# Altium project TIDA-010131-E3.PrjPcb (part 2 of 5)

## Sheet TIDA-010131-E3_LMK0482x _CLK_PWR.SchDoc: LMK0482x
size 431 x 279 mm; Date: Not shown in title block; ApprovedBy: Not shown in title block; CheckedBy: Not shown in title block; Author: Not shown in title block; CompanyName: Not shown in title block; DrawnBy: Avinash N; Engineer: Not shown in title block; Organization: Not shown in title block; Address1: Not shown in title block; Address2: Not shown in title block; Address3: Not shown in title block; Address4: Not shown in title block; DocumentNumber: 1; Revision: Use project parameter SCH_Rev; SheetNumber: 3; SheetTotal: 9; PageSetup: Record=PageOptions¦CenterHorizontal=True¦CenterVertical=True¦PrintScale=1.00¦XCorrection=1.00¦YCorrection=1.00¦PrintKind=0¦BorderSize=5000000¦LeftOffset=0¦BottomOffset=0¦Orientation=2¦PaperLength=1000¦PaperWidth=1000¦Scale=100¦PaperSource=15¦PrintQuality=600¦MediaType=1¦DitherType=10¦PaperKind=Letter¦PrintScaleMode=1
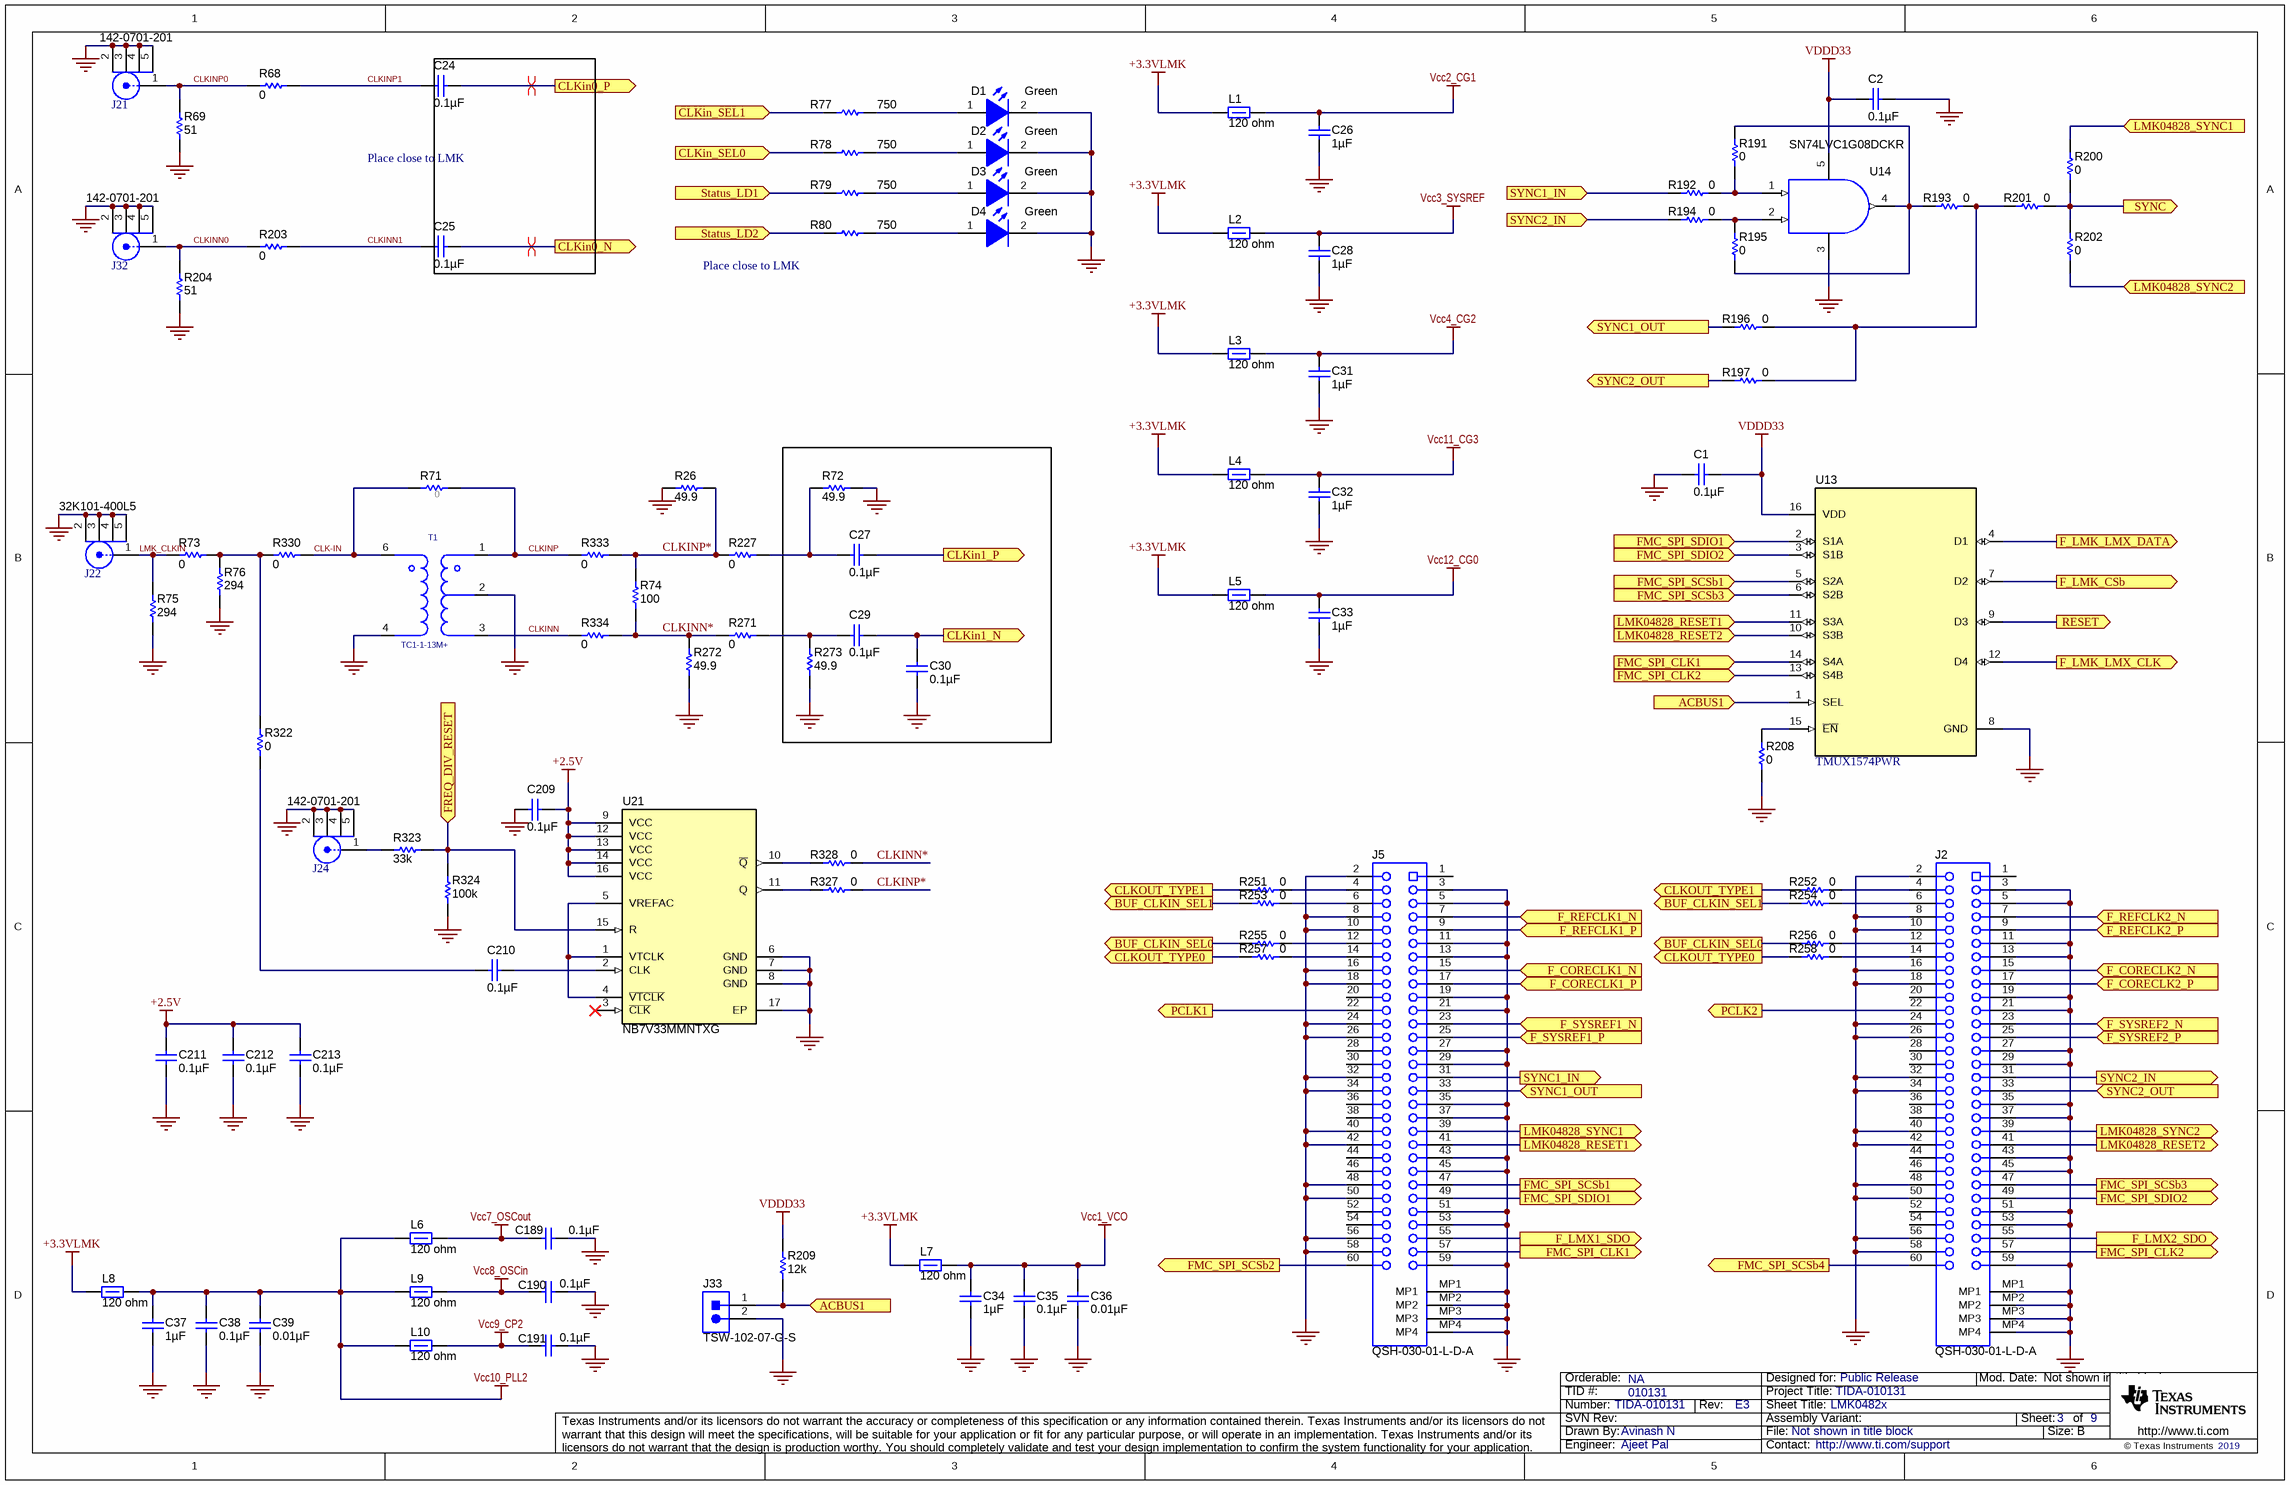
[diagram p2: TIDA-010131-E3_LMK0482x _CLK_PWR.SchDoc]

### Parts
C1  ValueDisplayed: 0.1µF  [0603]  (hidden comment: C0603C104J3RACTU)
C2  ValueDisplayed: 0.1µF  [0402]  (hidden comment: GRM155R71C104KA88D)
C24  ValueDisplayed: 0.1µF  [0201_033]  (hidden comment: GRM033R60J104KE19D)
C25  ValueDisplayed: 0.1µF  [0201_033]  (hidden comment: GRM033R60J104KE19D)
C26  ValueDisplayed: 1µF  [0402]  (hidden comment: C1005X7S1A105K050BC)
C27  ValueDisplayed: 0.1µF  [0201_033]  (hidden comment: GRM033R60J104KE19D)
C28  ValueDisplayed: 1µF  [0402]  (hidden comment: C1005X7S1A105K050BC)
C29  ValueDisplayed: 0.1µF  [0201_033]  (hidden comment: GRM033R60J104KE19D)
C30  ValueDisplayed: 0.1µF  [0201_033]  (hidden comment: GRM033R60J104KE19D)
C31  ValueDisplayed: 1µF  [0402]  (hidden comment: C1005X7S1A105K050BC)
C32  ValueDisplayed: 1µF  [0402]  (hidden comment: C1005X7S1A105K050BC)
C33  ValueDisplayed: 1µF  [0402]  (hidden comment: C1005X7S1A105K050BC)
C34  ValueDisplayed: 1µF  [0402]  (hidden comment: C1005X7S1A105K050BC)
C35  ValueDisplayed: 0.1µF  [0402]  (hidden comment: GRM155R71C104KA88D)
C36  ValueDisplayed: 0.01µF  [0402]  (hidden comment: GRM155R71E103KA01D)
C37  ValueDisplayed: 1µF  [0402]  (hidden comment: C1005X7S1A105K050BC)
C38  ValueDisplayed: 0.1µF  [0402]  (hidden comment: GRM155R71C104KA88D)
C39  ValueDisplayed: 0.01µF  [0402]  (hidden comment: GRM155R71E103KA01D)
C189  ValueDisplayed: 0.1µF  [0402]  (hidden comment: C1005X7R1E104M050BB)
C190  ValueDisplayed: 0.1µF  [0402]  (hidden comment: C1005X7R1E104M050BB)
C191  ValueDisplayed: 0.1µF  [0402]  (hidden comment: C1005X7R1E104M050BB)
C209  ValueDisplayed: 0.1µF  [0402]  (hidden comment: C1005X7R1E104M050BB)
C210  ValueDisplayed: 0.1µF  [0603]  (hidden comment: C0603C104J3RACTU)
C211  ValueDisplayed: 0.1µF  [0402]  (hidden comment: C1005X7R1E104M050BB)
C212  ValueDisplayed: 0.1µF  [0402]  (hidden comment: C1005X7R1E104M050BB)
C213  ValueDisplayed: 0.1µF  [0402]  (hidden comment: C1005X7R1E104M050BB)
D1  value Green  [LTST-C191_Green]  (hidden comment: LTST-C191TGKT)
D2  value Green  [LTST-C191_Green]  (hidden comment: LTST-C191TGKT)
D3  value Green  [LTST-C191_Green]  (hidden comment: LTST-C191TGKT)
D4  value Green  [LTST-C191_Green]  (hidden comment: LTST-C191TGKT)
J2  QSH-030-01-L-D-A  [Samtec_QSH-030-01-X-D-A]
J5  QSH-030-01-L-D-A  [Samtec_QSH-030-01-X-D-A]
J21  142-0701-201  [Johnson_142-0701-20x]
J22  32K101-400L5  [Rosenberger_32K101-400L5]
J24  142-0701-201  [Johnson_142-0701-20x]
J32  142-0701-201  [Johnson_142-0701-20x]
J33  TSW-102-07-G-S  [TSW-102-07-G-S]
L1  ValueDisplayed: 120 ohm  [0603]  (hidden comment: BLM18AG121SN1D)
L2  ValueDisplayed: 120 ohm  [0603]  (hidden comment: BLM18AG121SN1D)
L3  ValueDisplayed: 120 ohm  [0603]  (hidden comment: BLM18AG121SN1D)
L4  ValueDisplayed: 120 ohm  [0603]  (hidden comment: BLM18AG121SN1D)
L5  ValueDisplayed: 120 ohm  [0603]  (hidden comment: BLM18AG121SN1D)
L6  ValueDisplayed: 120 ohm  [0603]  (hidden comment: BLM18AG121SN1D)
L7  ValueDisplayed: 120 ohm  [0603]  (hidden comment: BLM18AG121SN1D)
L8  ValueDisplayed: 120 ohm  [0603]  (hidden comment: BLM18AG121SN1D)
L9  ValueDisplayed: 120 ohm  [0603]  (hidden comment: BLM18AG121SN1D)
L10  ValueDisplayed: 120 ohm  [0603]  (hidden comment: BLM18AG121SN1D)
R26  ValueDisplayed: 49.9  [0201]  (hidden comment: CRCW020149R9FKED)
R68  ValueDisplayed: 0  [0201]  (hidden comment: ERJ-1GN0R00C)
R69  ValueDisplayed: 51  [0201]  (hidden comment: RC0201JR-0751RL)
R71  ValueDisplayed: 0  [0603]  (hidden comment: CRCW06030000Z0EA)
R72  ValueDisplayed: 49.9  [0201]  (hidden comment: CRCW020149R9FKED)
R73  ValueDisplayed: 0  [0402]  (hidden comment: CRCW04020000Z0ED)
R74  ValueDisplayed: 100  [0201]  (hidden comment: RC0201FR-07100RL)
R75  ValueDisplayed: 294  [0402]  (hidden comment: CRCW0402294RFKED)
R76  ValueDisplayed: 294  [0402]  (hidden comment: CRCW0402294RFKED)
R77  ValueDisplayed: 750  [0603]  (hidden comment: CRCW0603750RFKEA)
R78  ValueDisplayed: 750  [0603]  (hidden comment: CRCW0603750RFKEA)
R79  ValueDisplayed: 750  [0603]  (hidden comment: CRCW0603750RFKEA)
R80  ValueDisplayed: 750  [0603]  (hidden comment: CRCW0603750RFKEA)
R191  ValueDisplayed: 0  [0402]  (hidden comment: CRCW04020000Z0ED)
R192  ValueDisplayed: 0  [0402]  (hidden comment: CRCW04020000Z0ED)
R193  ValueDisplayed: 0  [0402]  (hidden comment: CRCW04020000Z0ED)
R194  ValueDisplayed: 0  [0402]  (hidden comment: CRCW04020000Z0ED)
R195  ValueDisplayed: 0  [0402]  (hidden comment: CRCW04020000Z0ED)
R196  ValueDisplayed: 0  [0402]  (hidden comment: CRCW04020000Z0ED)
R197  ValueDisplayed: 0  [0402]  (hidden comment: CRCW04020000Z0ED)
R200  ValueDisplayed: 0  [0402]  (hidden comment: CRCW04020000Z0ED)
R201  ValueDisplayed: 0  [0402]  (hidden comment: CRCW04020000Z0ED)
R202  ValueDisplayed: 0  [0402]  (hidden comment: CRCW04020000Z0ED)
R203  ValueDisplayed: 0  [0201]  (hidden comment: ERJ-1GN0R00C)
R204  ValueDisplayed: 51  [0201]  (hidden comment: RC0201JR-0751RL)
R208  ValueDisplayed: 0  [0402]  (hidden comment: CRCW04020000Z0ED)
R209  ValueDisplayed: 12k  [0402]  (hidden comment: CRCW040212K0JNED)
R227  ValueDisplayed: 0  [0201]  (hidden comment: ERJ-1GN0R00C)
R251  ValueDisplayed: 0  [0402]  (hidden comment: CRCW04020000Z0ED)
R252  ValueDisplayed: 0  [0402]  (hidden comment: CRCW04020000Z0ED)
R253  ValueDisplayed: 0  [0402]  (hidden comment: CRCW04020000Z0ED)
R254  ValueDisplayed: 0  [0402]  (hidden comment: CRCW04020000Z0ED)
R255  ValueDisplayed: 0  [0402]  (hidden comment: CRCW04020000Z0ED)
R256  ValueDisplayed: 0  [0402]  (hidden comment: CRCW04020000Z0ED)
R257  ValueDisplayed: 0  [0402]  (hidden comment: CRCW04020000Z0ED)
R258  ValueDisplayed: 0  [0402]  (hidden comment: CRCW04020000Z0ED)
R271  ValueDisplayed: 0  [0201]  (hidden comment: ERJ-1GN0R00C)
R272  ValueDisplayed: 49.9  [0201]  (hidden comment: CRCW020149R9FKED)
R273  ValueDisplayed: 49.9  [0201]  (hidden comment: CRCW020149R9FKED)
R322  ValueDisplayed: 0  [0402]  (hidden comment: CRCW04020000Z0ED)
R323  ValueDisplayed: 33k  [0402]  (hidden comment: CRCW040233K0JNED)
R324  ValueDisplayed: 100k  [0402]  (hidden comment: CRCW0402100KFKED)
R327  ValueDisplayed: 0  [0201]  (hidden comment: ERJ-1GN0R00C)
R328  ValueDisplayed: 0  [0201]  (hidden comment: ERJ-1GN0R00C)
R330  ValueDisplayed: 0  [0402]  (hidden comment: CRCW04020000Z0ED)
R333  ValueDisplayed: 0  [0201]  (hidden comment: ERJ-1GN0R00C)
R334  ValueDisplayed: 0  [0201]  (hidden comment: ERJ-1GN0R00C)
T1  TC1-1-13M+  [TFMR_5_150x150_50]
U13  TMUX1574PWR  [PW0016A_N]
U14  SN74LVC1G08DCKR  [DCK0005A_N]
U21  NB7V33MMNTXG  [QFN16-3x3MM_0_5]

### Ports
ACBUS1 (in), BUF_CLKIN_SEL0 (out), BUF_CLKIN_SEL1 (out), CLKin0_N (out), CLKin0_P (out), CLKin1_N (out), CLKin1_P (out), CLKin_SEL0 (in), CLKin_SEL1 (in), CLKOUT_TYPE0 (out), CLKOUT_TYPE1 (out), F_CORECLK1_N (in), F_CORECLK1_P (in), F_CORECLK2_N (in), F_CORECLK2_P (in), F_LMK_CSb (out), F_LMK_LMX_CLK (out), F_LMK_LMX_DATA (out), F_LMX1_SDO (out), F_LMX2_SDO (out), F_REFCLK1_N (in), F_REFCLK1_P (in), F_REFCLK2_N (in), F_REFCLK2_P (in), F_SYSREF1_N (in), F_SYSREF1_P (in), F_SYSREF2_N (in), F_SYSREF2_P (in), FMC_SPI_CLK1 (in), FMC_SPI_CLK1 (out), FMC_SPI_CLK2 (in), FMC_SPI_CLK2 (out), FMC_SPI_SCSb1 (in), FMC_SPI_SCSb1 (out), FMC_SPI_SCSb2 (out), FMC_SPI_SCSb3 (in), FMC_SPI_SCSb3 (out), FMC_SPI_SCSb4 (out), FMC_SPI_SDIO1 (in), FMC_SPI_SDIO1 (out), FMC_SPI_SDIO2 (in), FMC_SPI_SDIO2 (out), FREQ_DIV_RESET (in), LMK04828_RESET1 (in), LMK04828_RESET1 (out), LMK04828_RESET2 (in), LMK04828_RESET2 (out), LMK04828_SYNC1 (in), LMK04828_SYNC1 (out), LMK04828_SYNC2 (in), LMK04828_SYNC2 (out), PCLK1 (out), PCLK2 (out), RESET (out), Status_LD1 (in), Status_LD2 (in), SYNC1_IN (in), SYNC1_IN (out), SYNC1_OUT (in), SYNC1_OUT (out), SYNC2_IN (in), SYNC2_IN (out), SYNC2_OUT (in), SYNC2_OUT (out), SYNC (out)

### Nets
+2.5V: C209.2 C211.2 C212.2 C213.2 U21.9(VCC) U21.12(VCC) U21.13(VCC) U21.14(VCC) U21.16(VCC)
+3.3VLMK: L1.1 L2.1 L3.1 L4.1 L5.1 L7.1 L8.1
GND: C1.1 C2.2 C26.2 C28.2 C30.1 C31.2 C32.2 C33.2 C34.2 C35.2 C36.2 C37.2 C38.2 C39.2 C189.2 C190.1 C191.1 C209.1 C211.1 C212.1 C213.1 D1.2(K) D2.2(K) D3.2(K) D4.2(K) J2.2 J2.3 J2.5 J2.8 J2.10 J2.11 J2.13 J2.16 J2.18 J2.19 J2.21 J2.24 J2.26 J2.27 J2.29 J2.32 J2.34 J2.35 J2.37 J2.40 J2.42 J2.43 J2.45 J2.48 J2.50 J2.51 J2.53 J2.56 J2.58 J2.59 J2.MP1 J2.MP2 J2.MP3 J2.MP4 J5.2 J5.3 J5.5 J5.8 J5.10 J5.11 J5.13 J5.16 J5.18 J5.19 J5.21 J5.24 J5.26 J5.27 J5.29 J5.32 J5.34 J5.35 J5.37 J5.40 J5.42 J5.43 J5.45 J5.48 J5.50 J5.51 J5.53 J5.56 J5.58 J5.59 J5.MP1 J5.MP2 J5.MP3 J5.MP4 J21.2 J21.3 J21.4 J21.5 J22.2 J22.3 J22.4 J22.5 J24.2 J24.3 J24.4 J24.5 J32.2 J32.3 J32.4 J32.5 J33.2 R26.1 R69.1 R72.2 R75.1 R76.1 R204.1 R208.1 R272.1 R273.1 R324.1 T1.2(secondary_ct) T1.4(primary) U13.8(GND) U14.3(V-) U21.6(GND) U21.7(GND) U21.8(GND) U21.17(EP)
Vcc1_VCO: C34.1 C35.1 C36.1 L7.2
Vcc2_CG1: C26.1 L1.2
Vcc3_SYSREF: C28.1 L2.2
Vcc4_CG2: C31.1 L3.2
Vcc7_OSCout: C189.1 L6.2
Vcc8_OSCin: C190.2 L9.2
Vcc9_CP2: C191.2 L10.2
Vcc10_PLL2: C37.1 C38.1 C39.1 L6.1 L8.2 L9.1 L10.1
Vcc11_CG3: C32.1 L4.2
Vcc12_CG0: C33.1 L5.2
VDDD33: C1.2 C2.1 R209.2 U13.16(VDD) U14.5(V+)
ACBUS1: J33.1 R209.1 U13.1(SEL) ; port ACBUS1
BUF_CLKIN_SEL0: R255.1 R256.1 ; port BUF_CLKIN_SEL0
BUF_CLKIN_SEL1: R253.1 R254.1 ; port BUF_CLKIN_SEL1
CLK-IN: R71.1 R330.2 T1.6(primary_dot)
CLKin0_N: C25.2 ; port CLKin0_N
CLKin0_P: C24.2 ; port CLKin0_P
CLKin1_N: C29.2 C30.2 ; port CLKin1_N
CLKin1_P: C27.2 ; port CLKin1_P
CLKin_SEL0: R78.1 ; port CLKin_SEL0
CLKin_SEL1: R77.1 ; port CLKin_SEL1
CLKINN: R334.1 T1.3(secondary)
CLKINN0: J32.1 R203.1 R204.2
CLKINN1: C25.1 R203.2
CLKINN*: R74.1 R271.1 R272.2 R328.1 R334.2
CLKINP: R71.2 R333.1 T1.1(secondary_dot)
CLKINP0: J21.1 R68.1 R69.2
CLKINP1: C24.1 R68.2
CLKINP*: R26.2 R74.2 R227.1 R327.1 R333.2
CLKOUT_TYPE0: R257.1 R258.1 ; port CLKOUT_TYPE0
CLKOUT_TYPE1: R251.1 R252.1 ; port CLKOUT_TYPE1
F_CORECLK1_N: J5.15 ; port F_CORECLK1_N
F_CORECLK1_P: J5.17 ; port F_CORECLK1_P
F_CORECLK2_N: J2.15 ; port F_CORECLK2_N
F_CORECLK2_P: J2.17 ; port F_CORECLK2_P
F_LMK_CSb: U13.7(D2) ; port F_LMK_CSb
F_LMK_LMX_CLK: U13.12(D4) ; port F_LMK_LMX_CLK
F_LMK_LMX_DATA: U13.4(D1) ; port F_LMK_LMX_DATA
F_LMX1_SDO: J5.55 ; port F_LMX1_SDO
F_LMX2_SDO: J2.55 ; port F_LMX2_SDO
F_REFCLK1_N: J5.7 ; port F_REFCLK1_N
F_REFCLK1_P: J5.9 ; port F_REFCLK1_P
F_REFCLK2_N: J2.7 ; port F_REFCLK2_N
F_REFCLK2_P: J2.9 ; port F_REFCLK2_P
F_SYSREF1_N: J5.23 ; port F_SYSREF1_N
F_SYSREF1_P: J5.25 ; port F_SYSREF1_P
F_SYSREF2_N: J2.23 ; port F_SYSREF2_N
F_SYSREF2_P: J2.25 ; port F_SYSREF2_P
FMC_SPI_CLK1: J5.57 U13.14(S4A) ; port FMC_SPI_CLK1
FMC_SPI_CLK2: J2.57 U13.13(S4B) ; port FMC_SPI_CLK2
FMC_SPI_SCSb1: J5.47 U13.5(S2A) ; port FMC_SPI_SCSb1
FMC_SPI_SCSb2: J5.60 ; port FMC_SPI_SCSb2
FMC_SPI_SCSb3: J2.47 U13.6(S2B) ; port FMC_SPI_SCSb3
FMC_SPI_SCSb4: J2.60 ; port FMC_SPI_SCSb4
FMC_SPI_SDIO1: J5.49 U13.2(S1A) ; port FMC_SPI_SDIO1
FMC_SPI_SDIO2: J2.49 U13.3(S1B) ; port FMC_SPI_SDIO2
FREQ_DIV_RESET: R323.2 R324.2 U21.15(R) ; port FREQ_DIV_RESET
LMK04828_RESET1: J5.41 U13.11(S3A) ; port LMK04828_RESET1
LMK04828_RESET2: J2.41 U13.10(S3B) ; port LMK04828_RESET2
LMK04828_SYNC1: J5.39 R200.1 ; port LMK04828_SYNC1
LMK04828_SYNC2: J2.39 R202.1 ; port LMK04828_SYNC2
LMK_CLKIN: J22.1 R73.1 R75.2
PCLK1: J5.22 ; port PCLK1
PCLK2: J2.22 ; port PCLK2
RESET: U13.9(D3) ; port RESET
Status_LD1: R79.1 ; port Status_LD1
Status_LD2: R80.1 ; port Status_LD2
SYNC: R200.2 R201.2 R202.2 ; port SYNC
SYNC1_IN: J5.31 R192.1 ; port SYNC1_IN
SYNC1_OUT: J5.33 R196.1 ; port SYNC1_OUT
SYNC2_IN: J2.31 R194.1 ; port SYNC2_IN
SYNC2_OUT: J2.33 R197.1 ; port SYNC2_OUT
NetC27_1: C27.1 R72.1 R227.2
NetC29_1: C29.1 R271.2 R273.2
NetC210_1: C210.1 R322.1
NetC210_2: C210.2 U21.2(CLK)
NetD1_1: D1.1(A) R77.2
NetD2_1: D2.1(A) R78.2
NetD3_1: D3.1(A) R79.2
NetD4_1: D4.1(A) R80.2
NetJ2_4: J2.4 R252.2
NetJ2_6: J2.6 R254.2
NetJ2_12: J2.12 R256.2
NetJ2_14: J2.14 R258.2
NetJ5_4: J5.4 R251.2
NetJ5_6: J5.6 R253.2
NetJ5_12: J5.12 R255.2
NetJ5_14: J5.14 R257.2
NetJ24_1: J24.1 R323.1
NetR73_2: R73.2 R76.2 R322.2 R330.1
NetR191_1: R191.1 R192.2 U14.1(A)
NetR191_2: R191.2 R193.1 R195.1 U14.4(Y)
NetR193_2: R193.2 R196.2 R197.2 R201.1
NetR194_2: R194.2 R195.2 U14.2(B)
NetR208_2: R208.2 U13.15(~{EN})
NetR327_2: R327.2 U21.11(Q)
NetR328_2: R328.2 U21.10(~{Q})
NetU21_1: U21.1(VTCLK) U21.4(~{VTCLK}) U21.5(VREFAC)

Not connected (* = marked no-connect by the designer): J2 1 20 28 30 36 38 44 46 52 54; J5 1 20 28 30 36 38 44 46 52 54; U21 3(~{CLK})*

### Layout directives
differential pair: CLKin0_N, CLKin0_P

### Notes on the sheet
- Place close to LMK
- (near R80) Place close to LMK

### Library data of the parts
C1 = C0603C104J3RACTU: CAP, CERM, 0.1uF, 25V, +/-5%, X7R, 0603; Manufacturer: Kemet; Polarized: N; TaMax_C: 125; TaMin_C: -55; Tolerance_%: 5; VDC_V: 25; Cap_F: 0.0000001; CompType: Capacitor; Value1: Unknown; U/M: EA
C2 C35 C38 = GRM155R71C104KA88D: CAP, CERM, 0.1 µF, 16 V, +/- 10%, X7R, 0402; Manufacturer: MuRata; Polarized: N; CompType: Capacitor; Value: 0.1uF; U/M: EA; Cap_F: 0.0000001; Tolerance_%: 10; Value1: Unknown; VDC_V: 16; Value2: 16V; TaMin_C: -55; TaMax_C: 125; SizeArea_mm2: 0.5; SizeAreaWB_mm2: 3; SizeX_mm: 1; SizeZ_mm: 0.6; AEC Category: Q200
C24 = grm033r60j104ke19d: CAP, CERM, 0.1 µF, 6.3 V, +/- 10%, X5R, 0201; Manufacturer: MuRata; Polarized: N; CompType: Capacitor; Value: 0.1uF; U/M: EA; Cap_F: 0.0000001; Tolerance_%: 10; Value1: Unknown; VDC_V: 6.3; Value2: 6.3V; TaMin_C: -55; TaMax_C: 85; Cap_Case: 0201; SizeArea_mm2: 0.18; SizeAreaWB_mm2: 2.08; SizeX_mm: 0.6; SizeY_mm: 0.3; SizeZ_mm: 0.33; AEC Category: Q200
C25 C27 C29 C30 = GRM033R60J104KE19D: CAP, CERM, 0.1 µF, 6.3 V, +/- 10%, X5R, 0201; Manufacturer: MuRata; Polarized: N; CompType: Capacitor; Value: 0.1uF; U/M: EA; Cap_F: 0.0000001; Tolerance_%: 10; Value1: Unknown; VDC_V: 6.3; Value2: 6.3V; TaMin_C: -55; TaMax_C: 85; Cap_Case: 0201; SizeArea_mm2: 0.18; SizeAreaWB_mm2: 2.08; SizeX_mm: 0.6; SizeY_mm: 0.3; SizeZ_mm: 0.33; AEC Category: Q200
C26 C28 C31-C34 C37 = C1005X7S1A105K050BC: CAP, CERM, 1 µF, 10 V, +/- 10%, X7S, 0402; Manufacturer: TDK; Polarized: N; CompType: Capacitor; Value: 1uF; U/M: EA; Cap_F: 0.000001; Tolerance_%: 10; ESR_ohm: 0.011416; Value1: 0.011416 ohm; Value2: 10V; IRMS_A: 1.483; TaMin_C: -55; TaMax_C: 125; SizeArea_mm2: 0.5; SizeAreaWB_mm2: 3; SizeX_mm: 1; SizeZ_mm: 0.6; AEC Category: Q200
C36 C39 = GRM155R71E103KA01D: CAP, CERM, 0.01 µF, 25 V, +/- 10%, X7R, 0402; Manufacturer: MuRata; Polarized: N; CompType: Capacitor; Value: 0.01uF; U/M: EA; Cap_F: 0.00000001; Tolerance_%: 10; Value1: Unknown; VDC_V: 25; Value2: 25V; TaMin_C: -55; TaMax_C: 125; SizeArea_mm2: 0.5; SizeAreaWB_mm2: 3; SizeX_mm: 1; SizeZ_mm: 0.6; AEC Category: Q200
C189-C191 = C1005X7R1E104M050BB: CAP, CERM, 0.1 µF, 25 V, +/- 20%, X7R, 0402; Manufacturer: TDK; Polarized: N; TaMax_C: 125; TaMin_C: -55; Tolerance_%: 20; VDC_V: 25; Cap_F: 0.0000001; CompType: Capacitor; Value: 0.1uF; Value1: Unknown; Value2: 25V; U/M: EA; SizeArea_mm2: 0.5; SizeAreaWB_mm2: 3; SizeX_mm: 1; SizeZ_mm: 0.6; AEC Category: Q200
C209 C211-C213 = C1005X7R1E104M050BB: CAP, CERM, 0.1 µF, 25 V,+/- 20%, X7R, 0402; Manufacturer: TDK; Polarized: N; TaMax_C: 125; TaMin_C: -55; Tolerance_%: 20; VDC_V: 25; Cap_F: 0.0000001; CompType: Capacitor; Value: 0.1uF; Value2: 25V; U/M: EA; SizeArea_mm2: 0.5; SizeAreaWB_mm2: 3; SizeX_mm: 1; SizeZ_mm: 0.6; AEC Category: Q200; Green_Lifecycle: NRND; Green_REACh: Passed
C210 = C0603C104J3RACTU: CAP, CERM, 0.1 µF, 25 V,+/- 5%, X7R, 0603; Manufacturer: Kemet; Polarized: N; TaMax_C: 125; TaMin_C: -55; Tolerance_%: 5; VDC_V: 25; Cap_F: 0.0000001; CompType: Capacitor; Value: 0.1uF; Value2: 25V; U/M: EA; SizeArea_mm2: 1.28; SizeAreaWB_mm2: 4.68; SizeX_mm: 1.6; SizeY_mm: 0.8; SizeZ_mm: 1; AEC Category: Q200; Green_Lifecycle: Active; Green_REACh: Passed
D1-D4 = LTST-C191TGKT: LED, Green, SMD; Manufacturer: Lite-On; Type: InGaN; Vf_V: 3.2; Value2: 3.2V; Io_A: 0.02; Value1: W; U/M: EA
J2 J5 = QSH-030-01-L-D-A: Receptacle, 0.5 mm, 30x2, Gold, TH; Manufacturer: Samtec; SymbolCreator: Altium; Pitch_mm: 0.5; Gender: Female; Shrouded: N; Row_Count: 2; RowSpacing_mm: 5.73
J21 J24 J32 = 142-0701-201: Connector, TH, SMA; Manufacturer: Emerson Network Power; SymbolCreator: X0208326
J22 = CMP-0077743-1: SMA, 50 Ohm, Gold, TH; Manufacturer: Rosenberger; Gender: Female; Voltage_V: 480V
J33 = TSW-102-07-G-S: Header, 100mil, 2x1, Gold, TH; Manufacturer: Samtec; SymbolCreator: a0412235; Pitch_mm: 2.54; Gender: Male; Shrouded: N; Row_Count: 1; Current_A: 6.3; Voltage_V: 550; Cert_CSA: Y
L1-L10 = BLM18AG121SN1D: Ferrite Bead, 120 ohm @ 100 MHz, 0.5 A, 0603; Manufacturer: MuRata; Value: 120 ohm; Imax_A: 0.5; DCR_ohm: 0.18; Value1: 0.18 ohm; Value2: 0.5A; SizeAreaWB_mm2: 4.68; SizeArea_mm2: 1.28; SizeX_mm: 1.6; SizeY_mm: 0.8; SizeZ_mm: 1; ZTyp@100MHz_Ohm: 120
R26 R72 R272 R273 = CRCW020149R9FKED: RES, 49.9, 1%, 0.05 W, 0201; Manufacturer: Vishay-Dale; CompType: Resistor; Value: 49.9; Value_Code: 49R9; Tolerance_%: 1; Power_W: 0.05; Value2: 0.05W; VDC_V: 30; TempCo: 100 ppm/C; SizeArea_mm2: 0.18; SizeX_mm: 0.6; SizeY_mm: 0.3; SizeZ_mm: 0.26; EIA_Code: E96; U/M: EA; AEC Category: Q200; AEC Qualified: N
R68 R203 R227 R271 R327 R328 R333 R334 = ERJ-1GN0R00C: RES, 0, 5%, 0.05 W, AEC-Q200 Grade 0, 0201; Manufacturer: Panasonic; CompType: Resistor; Tolerance_%: 5; Power_W: 0.05; Value: 0; U/M: EA; Value_Code: 0000; Value2: 0.05W; EIA_Code: E24; TempCo: ppm/C; SizeArea_mm2: 0.18; SizeX_mm: 0.6; SizeY_mm: 0.3; SizeZ_mm: 0.26; AEC Category: Q200; AEC Qualified: Y
R69 R204 = RC0201JR-0751RL: RES, 51, 5%, 0.05 W, 0201; Manufacturer: Yageo America; CompType: Resistor; Value: 51; Value_Code: 51R0; Tolerance_%: 5; Power_W: 0.05; Value2: 0.05W; VDC_V: 25; TempCo: 200 ppm/C; SizeArea_mm2: 0.18; SizeX_mm: 0.6; SizeY_mm: 0.3; SizeZ_mm: 0.26; EIA_Code: E24; U/M: EA; AEC Category: Q200; AEC Qualified: N
R71 = CRCW06030000Z0EA: RES, 0, 5%, 0.1 W, 0603; Manufacturer: Vishay-Dale; CompType: Resistor; Tolerance_%: 5; VDC_V: 75; Power_W: 0.1; Value: 0; U/M: EA; Value_Code: 0000; Value2: 0.1W; EIA_Code: E24; TempCo: 200 ppm/C; SizeArea_mm2: 1.28; SizeX_mm: 1.6; SizeY_mm: 0.8; SizeZ_mm: 1; AEC Category: Q200
R73 R322 R330 = CRCW04020000Z0ED: RES, 0, 5%, 0.063 W, 0402; Manufacturer: Vishay-Dale; CompType: Resistor; Tolerance_%: 5; VDC_V: 50; Power_W: 0.063; Value: 0; U/M: EA; Value_Code: 0000; Value2: 0.063W; EIA_Code: E24; TempCo: 200 ppm/C; SizeArea_mm2: 0.5; SizeX_mm: 1; SizeZ_mm: 0.6; AEC Category: Q200; Green_Lifecycle: Active; Green_REACh: Passed
R74 = rc0201fr-07100rl: RES, 100, 1%, 0.05 W, 0201; Manufacturer: Yageo America; CompType: Resistor; Value: 100; Value_Code: 100R; Tolerance_%: 1; Power_W: 0.05; Value2: 0.05W; VDC_V: 25; TempCo: 200 ppm/C; SizeArea_mm2: 0.18; SizeX_mm: 0.6; SizeY_mm: 0.3; SizeZ_mm: 0.26; EIA_Code: E96; U/M: EA; AEC Category: Q200; AEC Qualified: N
R75 R76 = CRCW0402294RFKED: RES, 294, 1%, 0.063 W, 0402; Manufacturer: Vishay-Dale; CompType: Resistor; Value: 294; Value_Code: 294R; Tolerance_%: 1; Power_W: 0.063; Value2: 0.063W; VDC_V: 50; TempCo: 100 ppm/C; SizeArea_mm2: 0.5; SizeZ_mm: 0.6; EIA_Code: E96; U/M: EA; AEC Category: Q200
R77-R80 = CRCW0603750RFKEA: RES, 750, 1%, 0.1 W, 0603; Manufacturer: Vishay-Dale; CompType: Resistor; Value: 750; Value_Code: 750R; Tolerance_%: 1; Power_W: 0.1; Value2: 0.1W; VDC_V: 75; TempCo: 100 ppm/C; SizeArea_mm2: 1.28; SizeX_mm: 1.6; SizeY_mm: 0.8; EIA_Code: E96; U/M: EA; AEC Category: Q200
R191-R197 R200-R202 R208 R251-R258 = CRCW04020000Z0ED: RES, 0, 5%, 0.063 W, 0402; Manufacturer: Vishay-Dale; CompType: Resistor; Value: 0; Value_Code: 0000; Tolerance_%: 5; Power_W: 0.063; Value2: 0.063W; VDC_V: 50; TempCo: 200 ppm/C; SizeArea_mm2: 0.5; SizeX_mm: 1; SizeZ_mm: 0.6; EIA_Code: E24; U/M: EA; AEC Category: Q200
R209 = CRCW040212K0JNED: RES, 12 k, 5%, 0.063 W, 0402; Manufacturer: Vishay-Dale; CompType: Resistor; Value: 12k; Res_ohm: 12000; Value_Code: 12k0; Tolerance_%: 5; Power_W: 0.063; Value2: 0.063W; VDC_V: 50; TempCo: 200 ppm/C; EIA_Code: E24; U/M: EA; AEC Category: Q200
R323 = CRCW040233K0JNED: RES, 33 k, 5%, 0.063 W, 0402; Manufacturer: Vishay-Dale; CompType: Resistor; Value: 33k; Res_ohm: 33000; Value_Code: 33k0; Tolerance_%: 5; Power_W: 0.063; Value2: 0.063W; VDC_V: 50; TempCo: 200 ppm/C; SizeArea_mm2: 0.5; SizeX_mm: 1; SizeZ_mm: 0.6; EIA_Code: E24; U/M: EA; AEC Category: Q200; Green_Lifecycle: Active; Green_REACh: Passed
R324 = CRCW0402100KFKED: RES, 100 k, 1%, 0.063 W, 0402; Manufacturer: Vishay-Dale; CompType: Resistor; Value: 100k; Res_ohm: 100000; Tolerance_%: 1; Power_W: 0.063; Value2: 0.063W; VDC_V: 50; TempCo: 100 ppm/C; SizeArea_mm2: 0.5; SizeZ_mm: 0.6; EIA_Code: E96; U/M: EA; AEC Category: Q200; Green_Lifecycle: Active; Green_REACh: Passed
T1 = TFMR_5_TC1-1-13M+: RF Transformers, Surface Mount, Config. G, Balanced Transmission Line, 0.50 - 6700 MHz; Manufacturer: Mini-Circuits
U13 = CMP-0086166-2: Low-capacitance, 2:1 (SPDT) 4-channel, powered-off protection switch with 1.8 V logic, PW0016A (TSSOP-16); Alternate Manufacturer: Texas Instruments; Alternate PartNumber: SN74CBTLV3257PWR; AEC Qualified: N; Rating: Catalog; SizeZ_mm: 1.2; CompType: IC; SizeArea_mm2: 32; AEC Category: Q200; SizeY_mm: 5; SizeAreaWB_mm2: 58.8; SizeX_mm: 6.4
U14 = SN74LVC1G08DCKR: Single 2-Input Positive-AND Gate, DCK0005A (SOT-5); Alternate PartNumber: SN74LVC1G08DCKT; Manufacturer: Texas Instruments; CompType: IC; SizeArea_mm2: 4.2; SizeAreaWB_mm2: 9.3; SizeX_mm: 2.1; SizeY_mm: 2; SizeZ_mm: 1.1; U/M: EA
U21 = NB7V32M: 1.8V / 2.5V, 10GHz ÷4 Clock Divider with CML Outputs, QFN-16; Manufacturer: ON Semiconductor

## Sheet TIDA-010131-E3_LMK00304_Buffer.SchDoc: LMK0482x
size 431 x 279 mm; Date: Not shown in title block; ApprovedBy: Not shown in title block; CheckedBy: Not shown in title block; Author: Not shown in title block; CompanyName: Not shown in title block; DrawnBy: Avinash N; Engineer: Not shown in title block; Organization: Not shown in title block; Address1: Not shown in title block; Address2: Not shown in title block; Address3: Not shown in title block; Address4: Not shown in title block; DocumentNumber: 1; Revision: Use project parameter SCH_Rev; SheetNumber: 4; SheetTotal: 9; PageSetup: Record=PageOptions¦CenterHorizontal=True¦CenterVertical=True¦PrintScale=1.00¦XCorrection=1.00¦YCorrection=1.00¦PrintKind=0¦BorderSize=5000000¦LeftOffset=0¦BottomOffset=0¦Orientation=2¦PaperLength=1000¦PaperWidth=1000¦Scale=100¦PaperSource=15¦PrintQuality=600¦MediaType=1¦DitherType=10¦PaperKind=Letter¦PrintScaleMode=1
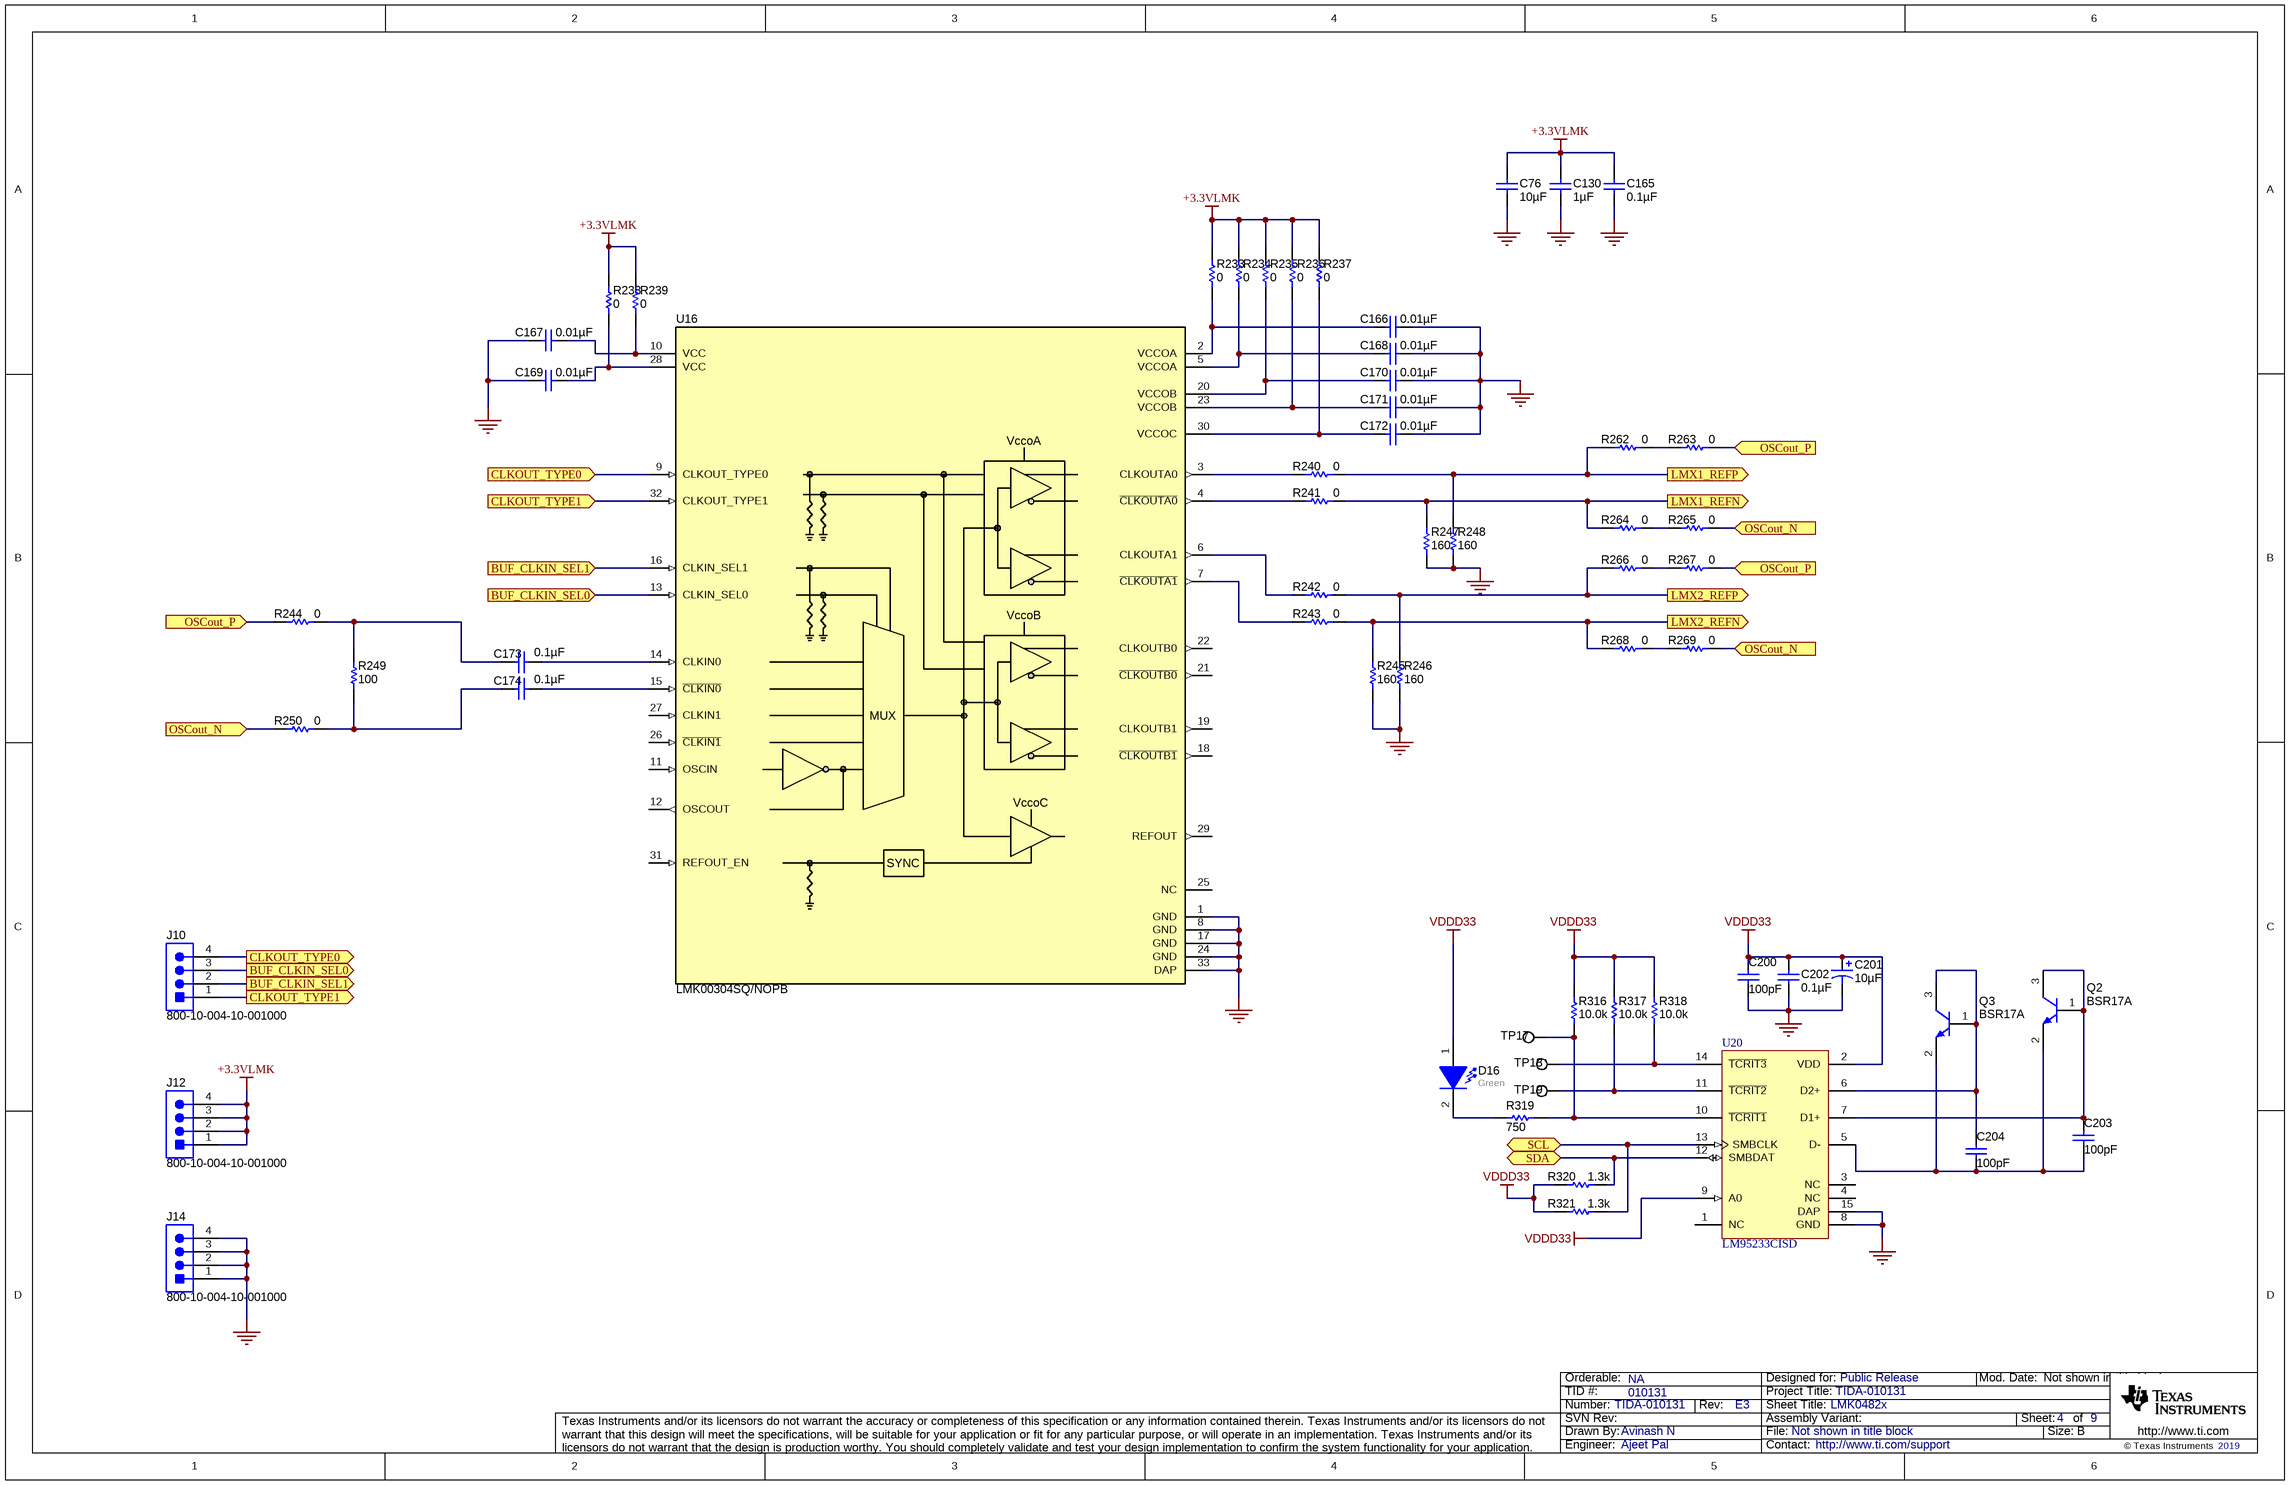
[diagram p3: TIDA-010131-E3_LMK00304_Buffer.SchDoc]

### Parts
C76  ValueDisplayed: 10µF  [0603]  (hidden comment: GRM188R61A106ME69D)
C130  ValueDisplayed: 1µF  [0402]  (hidden comment: C1005X7S1A105K050BC)
C165  ValueDisplayed: 0.1µF  [0402]  (hidden comment: GRM155R71C104KA88D)
C166  ValueDisplayed: 0.01µF  [0402]  (hidden comment: GRM155R71E103KA01D)
C167  ValueDisplayed: 0.01µF  [0402]  (hidden comment: GRM155R71E103KA01D)
C168  ValueDisplayed: 0.01µF  [0402]  (hidden comment: GRM155R71E103KA01D)
C169  ValueDisplayed: 0.01µF  [0402]  (hidden comment: GRM155R71E103KA01D)
C170  ValueDisplayed: 0.01µF  [0402]  (hidden comment: GRM155R71E103KA01D)
C171  ValueDisplayed: 0.01µF  [0402]  (hidden comment: GRM155R71E103KA01D)
C172  ValueDisplayed: 0.01µF  [0402]  (hidden comment: GRM155R71E103KA01D)
C173  ValueDisplayed: 0.1µF  [0402]  (hidden comment: C1005X7R1E104M050BB)
C174  ValueDisplayed: 0.1µF  [0402]  (hidden comment: C1005X7R1E104M050BB)
C200  ValueDisplayed: 100pF  [0402]  (hidden comment: GRM1555C1H101JA01D)
C201  ValueDisplayed: 10µF  [3528-21]  (hidden comment: 293D106X0010B2TE3)
C202  ValueDisplayed: 0.1µF  [0402]  (hidden comment: C1005X7R1E104M050BB)
C203  ValueDisplayed: 100pF  [0402]  (hidden comment: GRM1555C1H101JA01D)
C204  ValueDisplayed: 100pF  [0402]  (hidden comment: GRM1555C1H101JA01D)
D16  value Green  [LED_LTST-C190]  (hidden comment: LTST-C190GKT)
J10  800-10-004-10-001000  [Mill-Max_800-10-004-10-001000]
J12  800-10-004-10-001000  [Mill-Max_800-10-004-10-001000]
J14  800-10-004-10-001000  [Mill-Max_800-10-004-10-001000]
Q2  BSR17A  [SOT-23]
Q3  BSR17A  [SOT-23]
R233  ValueDisplayed: 0  [0402]  (hidden comment: CRCW04020000Z0ED)
R234  ValueDisplayed: 0  [0402]  (hidden comment: CRCW04020000Z0ED)
R235  ValueDisplayed: 0  [0402]  (hidden comment: CRCW04020000Z0ED)
R236  ValueDisplayed: 0  [0402]  (hidden comment: CRCW04020000Z0ED)
R237  ValueDisplayed: 0  [0402]  (hidden comment: CRCW04020000Z0ED)
R238  ValueDisplayed: 0  [0402]  (hidden comment: CRCW04020000Z0ED)
R239  ValueDisplayed: 0  [0402]  (hidden comment: CRCW04020000Z0ED)
R240  ValueDisplayed: 0  [0402]  (hidden comment: CRCW04020000Z0ED)
R241  ValueDisplayed: 0  [0402]  (hidden comment: CRCW04020000Z0ED)
R242  ValueDisplayed: 0  [0402]  (hidden comment: CRCW04020000Z0ED)
R243  ValueDisplayed: 0  [0402]  (hidden comment: CRCW04020000Z0ED)
R244  ValueDisplayed: 0  [0402]  (hidden comment: CRCW04020000Z0ED)
R245  ValueDisplayed: 160  [0402]  (hidden comment: CRCW0402160RJNED)
R246  ValueDisplayed: 160  [0402]  (hidden comment: CRCW0402160RJNED)
R247  ValueDisplayed: 160  [0402]  (hidden comment: CRCW0402160RJNED)
R248  ValueDisplayed: 160  [0402]  (hidden comment: CRCW0402160RJNED)
R249  ValueDisplayed: 100  [0402]  (hidden comment: CRCW0402100RFKED)
R250  ValueDisplayed: 0  [0402]  (hidden comment: CRCW04020000Z0ED)
R262  ValueDisplayed: 0  [0402]  (hidden comment: CRCW04020000Z0ED)
R263  ValueDisplayed: 0  [0402]  (hidden comment: CRCW04020000Z0ED)
R264  ValueDisplayed: 0  [0402]  (hidden comment: CRCW04020000Z0ED)
R265  ValueDisplayed: 0  [0402]  (hidden comment: CRCW04020000Z0ED)
R266  ValueDisplayed: 0  [0402]  (hidden comment: CRCW04020000Z0ED)
R267  ValueDisplayed: 0  [0402]  (hidden comment: CRCW04020000Z0ED)
R268  ValueDisplayed: 0  [0402]  (hidden comment: CRCW04020000Z0ED)
R269  ValueDisplayed: 0  [0402]  (hidden comment: CRCW04020000Z0ED)
R316  ValueDisplayed: 10.0k  [0402]  (hidden comment: ERJ-2RKF1002X)
R317  ValueDisplayed: 10.0k  [0402]  (hidden comment: ERJ-2RKF1002X)
R318  ValueDisplayed: 10.0k  [0402]  (hidden comment: ERJ-2RKF1002X)
R319  ValueDisplayed: 750  [0603]  (hidden comment: CRCW0603750RJNEA)
R320  ValueDisplayed: 1.3k  [0603]  (hidden comment: RC0603JR-071K3L)
R321  ValueDisplayed: 1.3k  [0603]  (hidden comment: RC0603JR-071K3L)
TP17  5007  [Keystone5007]  (value not drawn)
TP18  5007  [Keystone5007]  (value not drawn)
TP19  5007  [Keystone5007]  (value not drawn)
U16  LMK00304SQ/NOPB  [RTV0032A]
U20  LM95233CISD  [SDA14B]

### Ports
BUF_CLKIN_SEL0 (in), BUF_CLKIN_SEL0 (out), BUF_CLKIN_SEL1 (in), BUF_CLKIN_SEL1 (out), CLKOUT_TYPE0 (in), CLKOUT_TYPE0 (out), CLKOUT_TYPE1 (in), CLKOUT_TYPE1 (out), LMX1_REFN (out), LMX1_REFP (out), LMX2_REFN (out), LMX2_REFP (out), OSCout_N (in), OSCout_P (in), SCL (bidir), SDA (bidir)

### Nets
+3.3VLMK: C76.1 C130.1 C165.1 J12.1 J12.2 J12.3 J12.4 R233.2 R234.2 R235.2 R236.2 R237.2 R238.2 R239.2
GND: C76.2 C130.2 C165.2 C166.2 C167.1 C168.2 C169.1 C170.2 C171.2 C172.2 C200.2 C201.2(-) C202.2 J14.1 J14.2 J14.3 J14.4 R245.1 R246.1 R247.1 R248.1 U16.1(GND) U16.8(GND) U16.17(GND) U16.24(GND) U16.33(DAP) U20.8(GND) U20.15(DAP)
VDDD33: C200.1 C201.1(+) C202.1 D16.1(A) R316.2 R317.2 R318.2 R320.2 R321.2 U20.2(VDD) U20.9(A0)
BUF_CLKIN_SEL0: J10.3 U16.13(CLKIN_SEL0) ; port BUF_CLKIN_SEL0
BUF_CLKIN_SEL1: J10.2 U16.16(CLKIN_SEL1) ; port BUF_CLKIN_SEL1
CLKOUT_TYPE0: J10.4 U16.9(CLKOUT_TYPE0) ; port CLKOUT_TYPE0
CLKOUT_TYPE1: J10.1 U16.32(CLKOUT_TYPE1) ; port CLKOUT_TYPE1
LMX1_REFN: R241.2 R247.2 R264.1 ; port LMX1_REFN
LMX1_REFP: R240.2 R248.2 R262.1 ; port LMX1_REFP
LMX2_REFN: R243.2 R245.2 R268.1 ; port LMX2_REFN
LMX2_REFP: R242.2 R246.2 R266.1 ; port LMX2_REFP
OSCout_N: R250.1 R265.2 R269.2 ; port OSCout_N
OSCout_P: R244.1 R263.2 R267.2 ; port OSCout_P
SCL: R321.1 U20.13(SMBCLK) ; port SCL
SDA: R320.1 U20.12(SMBDAT) ; port SDA
NetC166_1: C166.1 R233.1 U16.2(VCCOA)
NetC167_2: C167.2 R239.1 U16.10(VCC)
NetC168_1: C168.1 R234.1 U16.5(VCCOA)
NetC169_2: C169.2 R238.1 U16.28(VCC)
NetC170_1: C170.1 R235.1 U16.20(VCCOB)
NetC171_1: C171.1 R236.1 U16.23(VCCOB)
NetC172_1: C172.1 R237.1 U16.30(VCCOC)
NetC173_1: C173.1 R244.2 R249.2
NetC173_2: C173.2 U16.14(CLKIN0)
NetC174_1: C174.1 R249.1 R250.2
NetC174_2: C174.2 U16.15(~{CLKIN0})
NetC203_1: C203.1 Q2.1(B) Q2.3(C) U20.7(D1+)
NetC203_2: C203.2 C204.2 Q2.2(E) Q3.2(E) U20.5(D-)
NetC204_1: C204.1 Q3.1(B) Q3.3(C) U20.6(D2+)
NetD16_2: D16.2(K) R319.2
NetR240_1: R240.1 U16.3(CLKOUTA0)
NetR241_1: R241.1 U16.4(~{CLKOUTA0})
NetR242_1: R242.1 U16.6(CLKOUTA1)
NetR243_1: R243.1 U16.7(~{CLKOUTA1})
NetR262_2: R262.2 R263.1
NetR264_2: R264.2 R265.1
NetR266_2: R266.2 R267.1
NetR268_2: R268.2 R269.1
NetR316_1: R316.1 R319.1 TP17.1 U20.10(~{TCRIT1})
NetR317_1: R317.1 TP19.1 U20.11(~{TCRIT2})
NetR318_1: R318.1 TP18.1 U20.14(~{TCRIT3})

Not connected (* = marked no-connect by the designer): U16 11(OSCIN) 12(OSCOUT) 18(~{CLKOUTB1}) 19(CLKOUTB1) 21(~{CLKOUTB0}) 22(CLKOUTB0) 25(NC) 26(~{CLKIN1}) 27(CLKIN1) 29(REFOUT) 31(REFOUT_EN); U20 1(NC) 3(NC) 4(NC)

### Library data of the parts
C76 = GRM188R61A106ME69D: CAP, CERM, 10 µF, 10 V, +/- 20%, X5R, 0603; Manufacturer: MuRata; Polarized: N; CompType: Capacitor; Value: 10uF; U/M: EA; Cap_F: 0.00001; Tolerance_%: 20; Value1: Unknown; VDC_V: 10; Value2: 10V; TaMin_C: -55; TaMax_C: 85; SizeArea_mm2: 1.28; SizeAreaWB_mm2: 4.68; SizeX_mm: 1.6; SizeY_mm: 0.8; SizeZ_mm: 1; AEC Category: Q200; Green_Lifecycle: Active; Green_REACh: Passed
C130 = C1005X7S1A105K050BC: as C26 on sheet TIDA-010131-E3_LMK0482x _CLK_PWR
C165 = GRM155R71C104KA88D: as C2 on sheet TIDA-010131-E3_LMK0482x _CLK_PWR
C166-C172 = GRM155R71E103KA01D: as C36 on sheet TIDA-010131-E3_LMK0482x _CLK_PWR
C173 C174 C202 = C1005X7R1E104M050BB: as C189-C191 on sheet TIDA-010131-E3_LMK0482x _CLK_PWR
C200 C203 C204 = GRM1555C1H101JA01D: CAP, CERM, 100 pF, 50 V, +/- 5%, C0G/NP0, 0402; Manufacturer: MuRata; Polarized: N; CompType: Capacitor; Value: 100pF; U/M: EA; Cap_F: 0.0000000001; Tolerance_%: 5; Value1: Unknown; VDC_V: 50; Value2: 50V; TaMin_C: -55; TaMax_C: 125; SizeArea_mm2: 0.5; SizeAreaWB_mm2: 3; SizeX_mm: 1; SizeZ_mm: 0.6; AEC Category: Q200
C201 = 293D106X0010B2TE3: CAP, TA, 10 µF, 10 V, +/- 20%, 2.5 ohm, SMD; Manufacturer: Vishay-Sprague; Polarized: Y; CompType: Capacitor; Value: 10uF; U/M: EA; Cap_F: 0.00001; Tolerance_%: 20; Value1: 2.5 ohm; VDC_V: 10; Value2: 10V; ESR_ohm: 2.5; IRMS_A: 0.18; TaMin_C: -55; TaMax_C: 125; Cap_Case: B; SizeAreaWB_mm2: 17.1; SizeArea_mm2: 9.8; SizeX_mm: 3.5; SizeY_mm: 2.8; SizeZ_mm: 2.1; AEC Category: Q200
D16 = LTST-C190GKT: LED, Green, SMD; Manufacturer: Lite-On; Vf_V: 2.1; Value2: 2.1V; Io_A: 0.02; Power_TotalModule: 0.1; Value1: 0.1W; U/M: EA
J10 J12 J14 = 800-10-004-10-001000: Header, 100mil, 4x1, TH; Manufacturer: Mill-Max; SymbolCreator: a0412235
Q2 Q3 = MMBT3904, Fairchild Semiconductor: TRANS NPN 40V 0.2A SOT-23; Manufacturer: ON Semiconductor; CompType: BJT; PNP: 0; NPN: 1; Vceo_V: 40; Vcesat1_V: 0.2; HfeMax: 300; TaMin_C: -55; TaMax_C: 150; SizeAreaWB_mm2: 14; SizeArea_mm2: 7.5; SizeX_mm: 2.5; SizeY_mm: 3; SizeZ_mm: 1.1; U/M: EA; AEC Category: Q101
R233-R244 R250 R262-R269 = CRCW04020000Z0ED: as R191-R197 on sheet TIDA-010131-E3_LMK0482x _CLK_PWR
R245-R248 = CRCW0402160RJNED: RES, 160, 5%, 0.063 W, 0402; Manufacturer: Vishay-Dale; CompType: Resistor; Value: 160; Value_Code: 160R; Tolerance_%: 5; Power_W: 0.063; Value2: 0.063W; VDC_V: 50; TempCo: 200 ppm/C; SizeArea_mm2: 0.5; SizeX_mm: 1; SizeZ_mm: 0.6; EIA_Code: E24; U/M: EA; AEC Category: Q200
R249 = CRCW0402100RFKED: RES, 100, 1%, 0.063 W, 0402; Manufacturer: Vishay-Dale; CompType: Resistor; Value: 100; Value_Code: 100R; Tolerance_%: 1; Power_W: 0.063; Value2: 0.063W; VDC_V: 50; TempCo: 100 ppm/C; SizeArea_mm2: 0.5; SizeZ_mm: 0.6; EIA_Code: E96; U/M: EA; AEC Category: Q200
R316-R318 = ERJ-2RKF1002X: RES, 10.0 k, 1%, 0.1 W, 0402; Manufacturer: Panasonic; CompType: Resistor; Value: 10.0k; Res_ohm: 10000; Value_Code: 10k0; Tolerance_%: 1; Power_W: 0.1; Value2: 0.1W; VDC_V: 50; TempCo: 100 ppm/C; SizeArea_mm2: 0.5; SizeZ_mm: 0.6; EIA_Code: E96; U/M: EA; AEC Category: Q200
R319 = CRCW0603750RJNEA: RES, 750, 5%, 0.1 W, 0603; Manufacturer: Vishay-Dale; CompType: Resistor; Value: 750; Value_Code: 750R; Tolerance_%: 5; Power_W: 0.1; Value2: 0.1W; VDC_V: 75; TempCo: 200 ppm/C; SizeArea_mm2: 1.28; SizeX_mm: 1.6; SizeY_mm: 0.8; SizeZ_mm: 1; EIA_Code: E24; U/M: EA; AEC Category: Q200
R320 R321 = RC0603JR-071K3L: RES, 1.3 k, 5%, 0.1 W, 0603; Manufacturer: Yageo America; CompType: Resistor; Value: 1.3k; Res_ohm: 1300; Value_Code: 1k30; Tolerance_%: 5; Power_W: 0.1; Value2: 0.1W; VDC_V: 50; TempCo: 100 ppm/C; SizeArea_mm2: 1.28; SizeX_mm: 1.6; SizeY_mm: 0.8; SizeZ_mm: 1; EIA_Code: E24; U/M: EA; AEC Category: Q200
TP17-TP19 = 5007: Test Point, Compact, White, TH; Manufacturer: Keystone; CompType: Test Point Loop; U/M: EA
U16 = LMK00304SQ/NOPB: 3.1-GHz Differential Clock Buffer/Level Translator, RTV0032A (WQFN-32); Manufacturer: Texas Instruments; SymbolCreator: a0411947; SizeArea_mm2: 25; SizeAreaWB_mm2: 49; SizeX_mm: 5; SizeZ_mm: 0.8; CompType: IC; U/M: EA
U20 = LM95233CISD: Dual Remote Diode and Local Temperature Sensor with SMBus Interface and TruTherm Technology, 15-pin LLP; Manufacturer: Texas Instruments; PackageTopMarking: NS*UZXYTT*95233CI; PowerWise: Y; CompType: Temp Sensor IC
